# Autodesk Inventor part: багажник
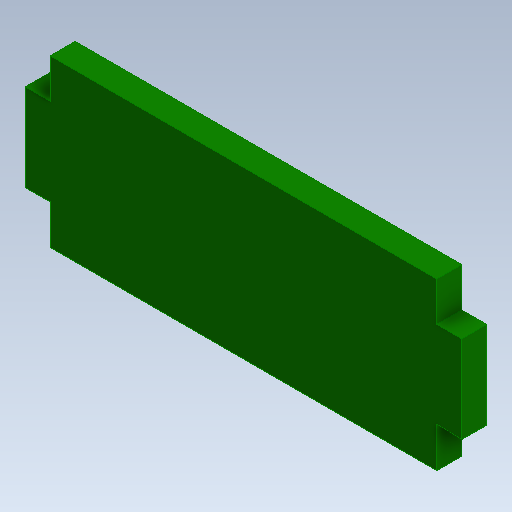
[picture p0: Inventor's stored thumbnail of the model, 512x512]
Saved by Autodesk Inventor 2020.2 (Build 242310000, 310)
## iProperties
Created: 2020-04
Part Number: багажник
Material: Типовые
Document SubType Name: Modeling
Designer: Алексей
Density: 1 g/cm^3
Appearance: По умолчанию
Author: Алексей
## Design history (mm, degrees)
sketch "Эскиз1"
  geometry: L1 (14, 13.558)-(14, -0.442) reference; L2 (10, 13.558)-(14, 13.558) reference; L3 (-52, 13.558)-(-52, -0.442) reference; L4 (-56, 13.558)-(-52, 13.558) reference; L5 (-56, -0.442)-(-56, 13.558) reference; L6 (-56, -0.442)-(-52, -0.442) reference; L7 (14, 19.867)-(10, 19.867) reference; L8 (-52, 19.867)-(-56, 19.867) reference; L9 (14, -6.751)-(10, -6.751) reference; L10 (-52, -6.751)-(-56, -6.751) reference; L11 (10, -6.751)-(-52, -6.751); L12 (-52, -6.751)-(-52, 19.867); L13 (-52, 19.867)-(10, 19.867); L14 (10, 19.867)-(10, -6.751); 5 further points; 2 other entities
  constraints: 8 end point, 2 parallel, 1 horizontal, 1 perpendicular, 2 other
extrude "Выдавливание1" new body sketch "Эскиз1" distance "d0" = 4; taper "d1" = 0 deg
node "Твердое тело1"
node "Ссылка1"
node "Ссылка2"
node "Ссылка3"
node "Ссылка4"
node "Ссылка5"
node "Ссылка6"
